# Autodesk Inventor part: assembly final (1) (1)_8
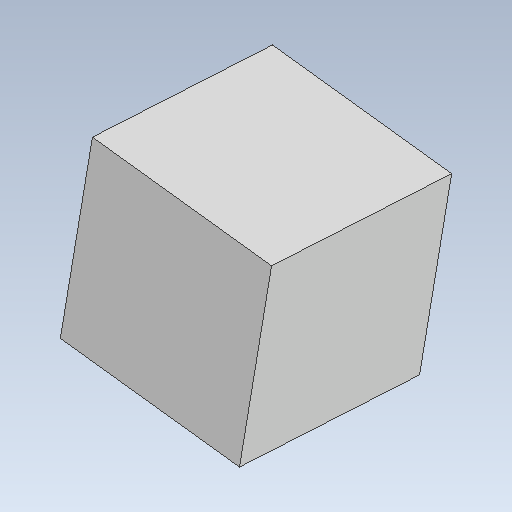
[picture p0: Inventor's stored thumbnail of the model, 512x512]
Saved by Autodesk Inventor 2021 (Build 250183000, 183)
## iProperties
Created: 2021-07
Part Number: assembly final (1) (1)_8
Material: Generic
Document SubType Name: Modeling
Designer: TARUN
Density: 1 g/cm^3
Appearance: Default
Author: TARUN
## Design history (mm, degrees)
feature "Base1"
body "Solid1"
